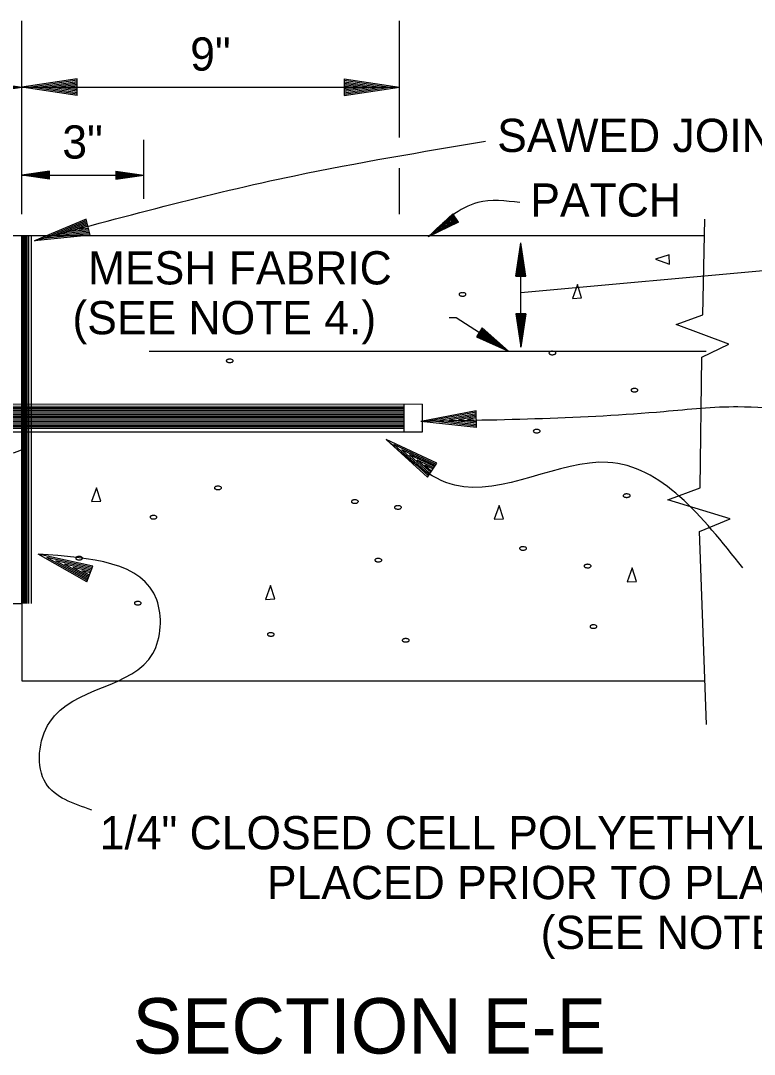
# Model space of a CAD drawing. Extents: x 1375738 to 1375905, y 380661 to 380875.
# Drawn here: x 1375756.82 to 1375767.42, y 380834.77 to 380849.71 of the extents above; entities that cross this region are included whole.
import ezdxf

# ---------------------------------------------------------------- set-up
doc = ezdxf.new("R2010")
doc.units = 0
doc.layers.add('R_Draft', color=7, linetype='Continuous')

msp = doc.modelspace()

# ---------------------------------------------------------------- linework, layer by layer
at = {"layer": 'R_Draft'}
for p, q in [((1375756.839, 380846.912), (1375756.839, 380849.708)), ((1375762.294, 380848.02), (1375762.294, 380849.708)), ((1375751.49, 380848.747), (1375756.839, 380848.747)), ((1375756.039, 380848.867), (1375756.839, 380848.747)), ((1375756.039, 380848.627), (1375756.839, 380848.747)), ((1375757.639, 380848.867), (1375756.839, 380848.747)), ((1375756.839, 380848.747), (1375762.294, 380848.747)), ((1375757.639, 380848.627), (1375756.839, 380848.747)), ((1375757.639, 380848.847), (1375756.973, 380848.747)), ((1375757.639, 380848.647), (1375756.973, 380848.747)), ((1375757.639, 380848.827), (1375757.111, 380848.747)), ((1375757.639, 380848.668), (1375757.111, 380848.747)), ((1375757.639, 380848.807), (1375757.244, 380848.747)), ((1375757.639, 380848.688), (1375757.244, 380848.747)), ((1375757.639, 380848.786), (1375757.379, 380848.747)), ((1375757.639, 380848.708), (1375757.379, 380848.747)), ((1375757.639, 380848.766), (1375757.513, 380848.747)), ((1375757.639, 380848.728), (1375757.513, 380848.747)), ((1375757.639, 380848.627), (1375757.639, 380848.867)), ((1375761.494, 380848.867), (1375762.294, 380848.747)), ((1375761.494, 380848.867), (1375761.494, 380848.627)), ((1375761.494, 380848.847), (1375762.16, 380848.747)), ((1375761.494, 380848.827), (1375762.023, 380848.747)), ((1375761.494, 380848.807), (1375761.889, 380848.747)), ((1375761.494, 380848.786), (1375761.754, 380848.747)), ((1375761.494, 380848.766), (1375761.62, 380848.747)), ((1375761.494, 380848.627), (1375762.294, 380848.747)), ((1375761.494, 380848.708), (1375761.754, 380848.747)), ((1375761.494, 380848.668), (1375762.023, 380848.747)), ((1375761.494, 380848.647), (1375762.16, 380848.747)), ((1375761.494, 380848.688), (1375761.889, 380848.747)), ((1375761.494, 380848.728), (1375761.62, 380848.747)), ((1375758.6, 380847.136), (1375758.6, 380847.985)), ((1375762.294, 380846.912), (1375762.294, 380847.578)), ((1375757.239, 380847.536), (1375756.839, 380847.476)), ((1375756.839, 380847.476), (1375758.6, 380847.476)), ((1375757.239, 380847.416), (1375756.839, 380847.476)), ((1375757.239, 380847.526), (1375756.906, 380847.476)), ((1375757.239, 380847.426), (1375756.906, 380847.476)), ((1375757.239, 380847.516), (1375756.975, 380847.476)), ((1375757.239, 380847.437), (1375756.975, 380847.476)), ((1375757.239, 380847.506), (1375757.041, 380847.476)), ((1375757.239, 380847.447), (1375757.041, 380847.476)), ((1375757.239, 380847.496), (1375757.109, 380847.476)), ((1375757.239, 380847.457), (1375757.109, 380847.476)), ((1375757.239, 380847.486), (1375757.176, 380847.476)), ((1375757.239, 380847.467), (1375757.176, 380847.476)), ((1375757.239, 380847.416), (1375757.239, 380847.536)), ((1375758.2, 380847.536), (1375758.6, 380847.476)), ((1375758.2, 380847.536), (1375758.2, 380847.416)), ((1375758.2, 380847.526), (1375758.533, 380847.476)), ((1375758.2, 380847.516), (1375758.465, 380847.476)), ((1375758.2, 380847.506), (1375758.398, 380847.476)), ((1375758.2, 380847.496), (1375758.33, 380847.476)), ((1375758.2, 380847.486), (1375758.263, 380847.476)), ((1375758.2, 380847.416), (1375758.6, 380847.476)), ((1375758.2, 380847.457), (1375758.33, 380847.476)), ((1375758.2, 380847.437), (1375758.465, 380847.476)), ((1375758.2, 380847.426), (1375758.533, 380847.476)), ((1375758.2, 380847.447), (1375758.398, 380847.476)), ((1375758.2, 380847.467), (1375758.263, 380847.476)), ((1375757.769, 380846.84), (1375757.022, 380846.529)), ((1375757.774, 380846.82), (1375757.151, 380846.562)), ((1375757.779, 380846.8), (1375757.285, 380846.595)), ((1375757.827, 380846.607), (1375757.769, 380846.84)), ((1375763.063, 380846.917), (1375762.709, 380846.584)), ((1375763.145, 380846.798), (1375762.709, 380846.584)), ((1375763.069, 380846.907), (1375762.775, 380846.63)), ((1375763.138, 380846.808), (1375762.775, 380846.63)), ((1375763.077, 380846.897), (1375762.843, 380846.677)), ((1375763.131, 380846.818), (1375762.843, 380846.677)), ((1375763.083, 380846.887), (1375762.909, 380846.722)), ((1375763.124, 380846.828), (1375762.909, 380846.722)), ((1375763.09, 380846.877), (1375762.975, 380846.769)), ((1375763.117, 380846.838), (1375762.975, 380846.769)), ((1375763.097, 380846.867), (1375763.041, 380846.814)), ((1375763.11, 380846.848), (1375763.041, 380846.814)), ((1375763.145, 380846.798), (1375763.063, 380846.917)), ((1375766.675, 380845.46), (1375766.706, 380846.838)), ((1375757.783, 380846.781), (1375757.414, 380846.627)), ((1375757.812, 380846.665), (1375757.414, 380846.627)), ((1375757.789, 380846.761), (1375757.546, 380846.66)), ((1375757.807, 380846.686), (1375757.546, 380846.66)), ((1375757.793, 380846.742), (1375757.675, 380846.692)), ((1375757.803, 380846.705), (1375757.675, 380846.692)), ((1375747.225, 380846.607), (1375756.842, 380846.602)), ((1375756.839, 380841.288), (1375756.839, 380846.602)), ((1375756.839, 380846.602), (1375766.701, 380846.602)), ((1375756.859, 380841.288), (1375756.859, 380846.602)), ((1375756.879, 380841.288), (1375756.879, 380846.602)), ((1375756.899, 380841.288), (1375756.899, 380846.602)), ((1375756.919, 380841.288), (1375756.919, 380846.602)), ((1375756.939, 380841.288), (1375756.939, 380846.602)), ((1375756.981, 380841.288), (1375756.981, 380846.602)), ((1375757.827, 380846.607), (1375757.022, 380846.529)), ((1375757.822, 380846.626), (1375757.151, 380846.562)), ((1375757.817, 380846.646), (1375757.285, 380846.595)), ((1375763.974, 380846.018), (1375764.046, 380846.498)), ((1375763.986, 380846.018), (1375764.046, 380846.418)), ((1375764.046, 380844.991), (1375764.046, 380846.498)), ((1375764.118, 380846.018), (1375764.046, 380846.498)), ((1375764.106, 380846.018), (1375764.046, 380846.418)), ((1375763.998, 380846.018), (1375764.046, 380846.335)), ((1375764.01, 380846.018), (1375764.046, 380846.255)), ((1375764.093, 380846.018), (1375764.046, 380846.335)), ((1375764.081, 380846.018), (1375764.046, 380846.255)), ((1375764.023, 380846.018), (1375764.046, 380846.174)), ((1375764.035, 380846.018), (1375764.046, 380846.094)), ((1375764.046, 380845.782), (1375768.479, 380846.183)), ((1375764.069, 380846.018), (1375764.046, 380846.174)), ((1375764.057, 380846.018), (1375764.046, 380846.094)), ((1375763.974, 380846.018), (1375764.118, 380846.018)), ((1375763.974, 380845.471), (1375764.046, 380844.991)), ((1375764.118, 380845.471), (1375763.974, 380845.471)), ((1375763.986, 380845.471), (1375764.046, 380845.071)), ((1375763.998, 380845.471), (1375764.046, 380845.154)), ((1375764.01, 380845.471), (1375764.046, 380845.234)), ((1375764.022, 380845.471), (1375764.046, 380845.315)), ((1375764.035, 380845.471), (1375764.046, 380845.395)), ((1375764.118, 380845.471), (1375764.046, 380844.991)), ((1375764.069, 380845.471), (1375764.046, 380845.315)), ((1375764.093, 380845.471), (1375764.046, 380845.154)), ((1375764.106, 380845.471), (1375764.046, 380845.071)), ((1375764.081, 380845.471), (1375764.046, 380845.234)), ((1375764.057, 380845.471), (1375764.046, 380845.395)), ((1375766.288, 380845.32), (1375766.675, 380845.46)), ((1375763.013, 380845.421), (1375763.113, 380845.421)), ((1375763.113, 380845.421), (1375763.867, 380844.933)), ((1375767.052, 380845.032), (1375766.288, 380845.32)), ((1375763.488, 380845.268), (1375763.407, 380845.142)), ((1375763.42, 380845.163), (1375763.725, 380845.025)), ((1375763.427, 380845.173), (1375763.655, 380845.07)), ((1375763.434, 380845.184), (1375763.584, 380845.116)), ((1375763.441, 380845.195), (1375763.514, 380845.162)), ((1375763.454, 380845.214), (1375763.514, 380845.162)), ((1375763.461, 380845.225), (1375763.584, 380845.116)), ((1375763.468, 380845.236), (1375763.655, 380845.07)), ((1375763.475, 380845.246), (1375763.725, 380845.025)), ((1375763.481, 380845.257), (1375763.797, 380844.978)), ((1375763.488, 380845.268), (1375763.867, 380844.933)), ((1375763.407, 380845.142), (1375763.867, 380844.933)), ((1375763.414, 380845.152), (1375763.797, 380844.978)), ((1375766.661, 380844.844), (1375767.052, 380845.032)), ((1375758.677, 380844.932), (1375766.725, 380844.934)), ((1375766.639, 380842.958), (1375766.661, 380844.844)), ((1375751.548, 380844.172), (1375762.629, 380844.166)), ((1375755.679, 380844.141), (1375762.36, 380844.137)), ((1375755.679, 380844.121), (1375762.36, 380844.117)), ((1375762.36, 380843.765), (1375762.36, 380844.166)), ((1375762.629, 380843.765), (1375762.629, 380844.166)), ((1375755.679, 380844.101), (1375762.36, 380844.097)), ((1375755.679, 380844.081), (1375762.36, 380844.077)), ((1375755.679, 380844.061), (1375762.36, 380844.057)), ((1375755.679, 380844.041), (1375762.36, 380844.037)), ((1375755.679, 380844.021), (1375762.36, 380844.017)), ((1375755.679, 380844.001), (1375762.36, 380843.997)), ((1375755.679, 380843.981), (1375762.36, 380843.977)), ((1375755.679, 380843.961), (1375762.36, 380843.957)), ((1375763.4, 380844.07), (1375762.605, 380843.918)), ((1375763.401, 380844.05), (1375762.739, 380843.924)), ((1375763.402, 380844.029), (1375762.876, 380843.929)), ((1375763.402, 380844.009), (1375763.01, 380843.934)), ((1375763.403, 380843.989), (1375763.145, 380843.94)), ((1375763.404, 380843.969), (1375763.279, 380843.945)), ((1375763.409, 380843.83), (1375763.4, 380844.07)), ((1375755.679, 380843.941), (1375762.36, 380843.937)), ((1375755.679, 380843.921), (1375762.36, 380843.917)), ((1375755.679, 380843.901), (1375762.36, 380843.897)), ((1375755.679, 380843.881), (1375762.36, 380843.877)), ((1375755.679, 380843.861), (1375762.36, 380843.857)), ((1375755.679, 380843.841), (1375762.36, 380843.837)), ((1375755.679, 380843.821), (1375762.36, 380843.817)), ((1375763.409, 380843.83), (1375762.605, 380843.918)), ((1375763.409, 380843.85), (1375762.739, 380843.924)), ((1375763.408, 380843.87), (1375762.876, 380843.929)), ((1375763.407, 380843.89), (1375763.01, 380843.934)), ((1375763.406, 380843.911), (1375763.145, 380843.94)), ((1375763.405, 380843.931), (1375763.279, 380843.945)), ((1375751.547, 380843.771), (1375762.629, 380843.765)), ((1375762.701, 380843.114), (1375762.102, 380843.658)), ((1375762.834, 380843.314), (1375762.102, 380843.658)), ((1375762.712, 380843.131), (1375762.213, 380843.584)), ((1375762.823, 380843.297), (1375762.213, 380843.584)), ((1375762.811, 380843.28), (1375762.327, 380843.508)), ((1375762.723, 380843.148), (1375762.327, 380843.508)), ((1375762.734, 380843.164), (1375762.438, 380843.434)), ((1375762.8, 380843.264), (1375762.438, 380843.434)), ((1375762.789, 380843.247), (1375762.551, 380843.358)), ((1375762.746, 380843.182), (1375762.551, 380843.358)), ((1375762.778, 380843.23), (1375762.662, 380843.284)), ((1375762.757, 380843.198), (1375762.662, 380843.284)), ((1375762.701, 380843.114), (1375762.834, 380843.314)), ((1375766.168, 380842.783), (1375766.639, 380842.958)), ((1375767.071, 380842.51), (1375766.168, 380842.783)), ((1375766.625, 380842.326), (1375767.071, 380842.51)), ((1375766.727, 380839.537), (1375766.625, 380842.326)), ((1375757.78, 380841.6), (1375757.077, 380842.001)), ((1375757.866, 380841.824), (1375757.077, 380842.001)), ((1375757.787, 380841.619), (1375757.201, 380841.953)), ((1375757.859, 380841.806), (1375757.201, 380841.953)), ((1375757.852, 380841.787), (1375757.33, 380841.903)), ((1375757.794, 380841.638), (1375757.33, 380841.903)), ((1375757.801, 380841.657), (1375757.454, 380841.855)), ((1375757.845, 380841.768), (1375757.454, 380841.855)), ((1375757.837, 380841.749), (1375757.581, 380841.806)), ((1375757.809, 380841.676), (1375757.581, 380841.806)), ((1375757.83, 380841.73), (1375757.705, 380841.758)), ((1375757.816, 380841.695), (1375757.705, 380841.758)), ((1375757.78, 380841.6), (1375757.866, 380841.824)), ((1375747.222, 380841.294), (1375756.839, 380841.288)), ((1375756.839, 380841.288), (1375756.839, 380840.169)), ((1375756.839, 380840.169), (1375766.701, 380840.169))]:
    msp.add_line(p, q, dxfattribs=at)
for points in [[(1375765.994, 380846.263), (1375766.194, 380846.19), (1375766.188, 380846.323), (1375765.994, 380846.263)], [(1375764.866, 380845.895), (1375764.793, 380845.695), (1375764.925, 380845.701), (1375764.866, 380845.895)], [(1375751.366, 380843.466), (1375751.79, 380843.41), (1375752.496, 380843.438), (1375752.609, 380843.523), (1375752.919, 380843.495), (1375753.541, 380843.438), (1375753.851, 380843.495), (1375753.936, 380843.551), (1375754.247, 380843.579), (1375754.501, 380843.495), (1375754.727, 380843.495), (1375755.376, 380843.608), (1375755.546, 380843.466), (1375756.111, 380843.495), (1375756.393, 380843.523), (1375756.393, 380843.41), (1375756.732, 380843.466), (1375756.873, 380843.523)], [(1375757.919, 380842.958), (1375757.846, 380842.758), (1375757.979, 380842.764), (1375757.919, 380842.958)], [(1375763.736, 380842.704), (1375763.663, 380842.504), (1375763.796, 380842.51), (1375763.736, 380842.704)], [(1375765.657, 380841.8), (1375765.584, 380841.6), (1375765.716, 380841.606), (1375765.657, 380841.8)], [(1375760.432, 380841.546), (1375760.359, 380841.346), (1375760.492, 380841.352), (1375760.432, 380841.546)]]:
    msp.add_lwpolyline(points, dxfattribs=at)
for points in [[(1375757.022, 380846.529), (1375760.777, 380847.468), (1375763.537, 380847.965)], [(1375764.034, 380847.081), (1375763.427, 380847.081), (1375762.709, 380846.584)], [(1375763.204, 380845.778), (1375763.221, 380845.776), (1375763.242, 380845.769), (1375763.252, 380845.759), (1375763.254, 380845.753), (1375763.248, 380845.742), (1375763.242, 380845.737), (1375763.23, 380845.732), (1375763.213, 380845.728), (1375763.204, 380845.728), (1375763.191, 380845.729), (1375763.176, 380845.732), (1375763.165, 380845.737), (1375763.155, 380845.746), (1375763.154, 380845.753), (1375763.157, 380845.762), (1375763.165, 380845.769), (1375763.173, 380845.772), (1375763.185, 380845.776), (1375763.193, 380845.778), (1375763.204, 380845.778)], [(1375764.503, 380844.931), (1375764.52, 380844.929), (1375764.541, 380844.922), (1375764.551, 380844.912), (1375764.553, 380844.906), (1375764.547, 380844.895), (1375764.541, 380844.89), (1375764.529, 380844.885), (1375764.511, 380844.881), (1375764.503, 380844.881), (1375764.489, 380844.882), (1375764.475, 380844.885), (1375764.464, 380844.89), (1375764.454, 380844.899), (1375764.453, 380844.906), (1375764.456, 380844.916), (1375764.464, 380844.922), (1375764.472, 380844.926), (1375764.484, 380844.929), (1375764.491, 380844.931), (1375764.503, 380844.931)], [(1375759.843, 380844.818), (1375759.861, 380844.816), (1375759.881, 380844.809), (1375759.892, 380844.799), (1375759.893, 380844.793), (1375759.888, 380844.782), (1375759.882, 380844.777), (1375759.869, 380844.772), (1375759.852, 380844.768), (1375759.843, 380844.768), (1375759.83, 380844.769), (1375759.816, 380844.772), (1375759.805, 380844.777), (1375759.795, 380844.786), (1375759.793, 380844.793), (1375759.797, 380844.802), (1375759.805, 380844.809), (1375759.813, 380844.812), (1375759.825, 380844.816), (1375759.832, 380844.818), (1375759.843, 380844.818)], [(1375765.689, 380844.394), (1375765.706, 380844.392), (1375765.727, 380844.385), (1375765.737, 380844.375), (1375765.739, 380844.369), (1375765.733, 380844.358), (1375765.727, 380844.354), (1375765.715, 380844.348), (1375765.697, 380844.344), (1375765.689, 380844.344), (1375765.675, 380844.346), (1375765.661, 380844.348), (1375765.65, 380844.353), (1375765.64, 380844.362), (1375765.639, 380844.369), (1375765.642, 380844.379), (1375765.65, 380844.385), (1375765.658, 380844.389), (1375765.67, 380844.392), (1375765.677, 380844.394), (1375765.689, 380844.394)], [(1375767.95, 380844.081), (1375767.183, 380844.127), (1375766.114, 380844.058), (1375762.605, 380843.918)], [(1375764.277, 380843.802), (1375764.295, 380843.8), (1375764.315, 380843.792), (1375764.325, 380843.782), (1375764.327, 380843.776), (1375764.321, 380843.766), (1375764.315, 380843.761), (1375764.303, 380843.755), (1375764.286, 380843.752), (1375764.277, 380843.752), (1375764.264, 380843.753), (1375764.249, 380843.755), (1375764.239, 380843.76), (1375764.229, 380843.77), (1375764.227, 380843.776), (1375764.23, 380843.786), (1375764.238, 380843.792), (1375764.246, 380843.796), (1375764.258, 380843.8), (1375764.266, 380843.801), (1375764.277, 380843.802)], [(1375767.253, 380841.803), (1375765.304, 380843.326), (1375763.095, 380842.995), (1375762.102, 380843.658)], [(1375759.674, 380842.982), (1375759.691, 380842.98), (1375759.712, 380842.973), (1375759.722, 380842.963), (1375759.724, 380842.957), (1375759.718, 380842.946), (1375759.712, 380842.942), (1375759.7, 380842.936), (1375759.683, 380842.932), (1375759.674, 380842.932), (1375759.661, 380842.934), (1375759.646, 380842.936), (1375759.635, 380842.941), (1375759.625, 380842.95), (1375759.624, 380842.957), (1375759.627, 380842.967), (1375759.635, 380842.973), (1375759.643, 380842.977), (1375759.655, 380842.98), (1375759.663, 380842.982), (1375759.674, 380842.982)], [(1375761.651, 380842.785), (1375761.668, 380842.783), (1375761.689, 380842.776), (1375761.699, 380842.766), (1375761.701, 380842.76), (1375761.695, 380842.749), (1375761.689, 380842.744), (1375761.677, 380842.738), (1375761.659, 380842.735), (1375761.651, 380842.735), (1375761.637, 380842.736), (1375761.623, 380842.738), (1375761.612, 380842.744), (1375761.602, 380842.753), (1375761.601, 380842.76), (1375761.604, 380842.769), (1375761.612, 380842.776), (1375761.62, 380842.779), (1375761.632, 380842.783), (1375761.639, 380842.784), (1375761.651, 380842.785)], [(1375765.576, 380842.87), (1375765.593, 380842.868), (1375765.614, 380842.86), (1375765.624, 380842.85), (1375765.626, 380842.844), (1375765.62, 380842.834), (1375765.614, 380842.829), (1375765.602, 380842.823), (1375765.585, 380842.82), (1375765.576, 380842.82), (1375765.563, 380842.821), (1375765.548, 380842.823), (1375765.537, 380842.828), (1375765.527, 380842.838), (1375765.526, 380842.844), (1375765.529, 380842.854), (1375765.537, 380842.86), (1375765.545, 380842.864), (1375765.557, 380842.868), (1375765.565, 380842.869), (1375765.576, 380842.87)], [(1375762.272, 380842.7), (1375762.289, 380842.698), (1375762.31, 380842.691), (1375762.32, 380842.681), (1375762.322, 380842.675), (1375762.316, 380842.664), (1375762.31, 380842.659), (1375762.298, 380842.654), (1375762.281, 380842.65), (1375762.272, 380842.65), (1375762.259, 380842.651), (1375762.244, 380842.654), (1375762.233, 380842.659), (1375762.223, 380842.668), (1375762.222, 380842.675), (1375762.225, 380842.684), (1375762.233, 380842.691), (1375762.241, 380842.694), (1375762.253, 380842.698), (1375762.261, 380842.7), (1375762.272, 380842.7)], [(1375758.742, 380842.559), (1375758.759, 380842.557), (1375758.78, 380842.55), (1375758.79, 380842.54), (1375758.792, 380842.534), (1375758.786, 380842.523), (1375758.78, 380842.518), (1375758.768, 380842.512), (1375758.751, 380842.509), (1375758.742, 380842.509), (1375758.729, 380842.51), (1375758.714, 380842.512), (1375758.703, 380842.518), (1375758.693, 380842.527), (1375758.692, 380842.534), (1375758.695, 380842.543), (1375758.703, 380842.55), (1375758.711, 380842.553), (1375758.723, 380842.557), (1375758.731, 380842.558), (1375758.742, 380842.559)], [(1375764.079, 380842.107), (1375764.097, 380842.105), (1375764.117, 380842.098), (1375764.127, 380842.088), (1375764.129, 380842.082), (1375764.123, 380842.071), (1375764.117, 380842.066), (1375764.105, 380842.061), (1375764.088, 380842.057), (1375764.079, 380842.057), (1375764.066, 380842.058), (1375764.051, 380842.061), (1375764.041, 380842.066), (1375764.031, 380842.075), (1375764.029, 380842.082), (1375764.032, 380842.092), (1375764.04, 380842.098), (1375764.048, 380842.102), (1375764.06, 380842.105), (1375764.068, 380842.107), (1375764.079, 380842.107)], [(1375757.85, 380838.302), (1375757.187, 380838.688), (1375757.243, 380839.572), (1375758.733, 380840.566), (1375758.789, 380841.339), (1375757.077, 380842.001)], [(1375757.669, 380841.966), (1375757.687, 380841.964), (1375757.707, 380841.957), (1375757.717, 380841.947), (1375757.719, 380841.941), (1375757.713, 380841.93), (1375757.707, 380841.925), (1375757.695, 380841.92), (1375757.678, 380841.916), (1375757.669, 380841.916), (1375757.656, 380841.917), (1375757.641, 380841.92), (1375757.631, 380841.925), (1375757.621, 380841.934), (1375757.619, 380841.941), (1375757.622, 380841.95), (1375757.63, 380841.957), (1375757.638, 380841.96), (1375757.65, 380841.964), (1375757.658, 380841.966), (1375757.669, 380841.966)], [(1375761.989, 380841.938), (1375762.007, 380841.936), (1375762.027, 380841.928), (1375762.038, 380841.918), (1375762.039, 380841.912), (1375762.034, 380841.902), (1375762.028, 380841.897), (1375762.015, 380841.891), (1375761.998, 380841.888), (1375761.989, 380841.888), (1375761.976, 380841.889), (1375761.962, 380841.891), (1375761.951, 380841.896), (1375761.941, 380841.906), (1375761.939, 380841.912), (1375761.943, 380841.922), (1375761.951, 380841.928), (1375761.959, 380841.932), (1375761.971, 380841.936), (1375761.978, 380841.937), (1375761.989, 380841.938)], [(1375765.011, 380841.853), (1375765.029, 380841.851), (1375765.049, 380841.844), (1375765.059, 380841.834), (1375765.061, 380841.828), (1375765.055, 380841.817), (1375765.049, 380841.812), (1375765.037, 380841.806), (1375765.02, 380841.803), (1375765.011, 380841.803), (1375764.998, 380841.804), (1375764.983, 380841.806), (1375764.973, 380841.812), (1375764.963, 380841.821), (1375764.961, 380841.828), (1375764.964, 380841.837), (1375764.972, 380841.844), (1375764.98, 380841.847), (1375764.992, 380841.851), (1375765, 380841.852), (1375765.011, 380841.853)], [(1375758.516, 380841.316), (1375758.534, 380841.314), (1375758.554, 380841.307), (1375758.565, 380841.297), (1375758.566, 380841.291), (1375758.561, 380841.28), (1375758.555, 380841.276), (1375758.542, 380841.27), (1375758.525, 380841.266), (1375758.516, 380841.266), (1375758.503, 380841.268), (1375758.489, 380841.27), (1375758.478, 380841.275), (1375758.468, 380841.284), (1375758.466, 380841.291), (1375758.469, 380841.301), (1375758.477, 380841.307), (1375758.485, 380841.311), (1375758.497, 380841.314), (1375758.505, 380841.316), (1375758.516, 380841.316)], [(1375765.096, 380840.978), (1375765.113, 380840.976), (1375765.134, 380840.968), (1375765.144, 380840.958), (1375765.146, 380840.952), (1375765.14, 380840.942), (1375765.134, 380840.937), (1375765.122, 380840.931), (1375765.105, 380840.928), (1375765.096, 380840.928), (1375765.083, 380840.929), (1375765.068, 380840.931), (1375765.057, 380840.936), (1375765.047, 380840.946), (1375765.046, 380840.952), (1375765.049, 380840.962), (1375765.057, 380840.968), (1375765.065, 380840.972), (1375765.077, 380840.976), (1375765.085, 380840.977), (1375765.096, 380840.978)], [(1375760.436, 380840.864), (1375760.454, 380840.862), (1375760.474, 380840.855), (1375760.485, 380840.845), (1375760.486, 380840.839), (1375760.481, 380840.828), (1375760.475, 380840.824), (1375760.462, 380840.818), (1375760.445, 380840.814), (1375760.436, 380840.814), (1375760.423, 380840.816), (1375760.409, 380840.818), (1375760.398, 380840.823), (1375760.388, 380840.832), (1375760.386, 380840.839), (1375760.389, 380840.849), (1375760.397, 380840.855), (1375760.405, 380840.859), (1375760.417, 380840.862), (1375760.425, 380840.864), (1375760.436, 380840.864)], [(1375762.385, 380840.78), (1375762.402, 380840.778), (1375762.423, 380840.771), (1375762.433, 380840.761), (1375762.435, 380840.755), (1375762.429, 380840.744), (1375762.423, 380840.739), (1375762.411, 380840.734), (1375762.393, 380840.73), (1375762.385, 380840.73), (1375762.371, 380840.731), (1375762.357, 380840.734), (1375762.346, 380840.739), (1375762.336, 380840.748), (1375762.335, 380840.755), (1375762.338, 380840.764), (1375762.346, 380840.771), (1375762.354, 380840.774), (1375762.366, 380840.778), (1375762.373, 380840.78), (1375762.385, 380840.78)]]:
    msp.add_spline(points, degree=3, dxfattribs=at)

# ---------------------------------------------------------------- texts
for s, height, p in [('9"', 0.48, (1375759.272, 380848.987)), ('SAWED JOINT AND JOINT SEALANT', 0.48, (1375763.706, 380847.811)), ('3"', 0.48, (1375757.425, 380847.716)), ('PATCH', 0.48, (1375764.184, 380846.877)), ('MESH FABRIC', 0.48, (1375757.796, 380845.897)), ('(SEE NOTE 4.)', 0.48, (1375757.571, 380845.177)), ('1/4" CLOSED CELL POLYETHYLENE FOAM TO BE', 0.48, (1375757.965, 380837.734)), ('PLACED PRIOR TO PLACING PATCH.', 0.48, (1375760.38, 380837.014)), ('(SEE NOTE 6)', 0.48, (1375764.333, 380836.294)), ('SECTION E-E', 0.8, (1375758.44, 380834.783))]:
    msp.add_text(s, height=height, dxfattribs=at).set_placement(p)

doc.saveas('drawing.dxf')
